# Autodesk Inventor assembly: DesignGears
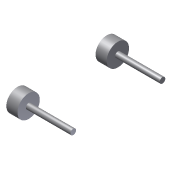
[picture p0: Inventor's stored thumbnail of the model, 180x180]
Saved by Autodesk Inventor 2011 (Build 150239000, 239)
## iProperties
Created: 2007-12
Part Number: DesignGears
Document SubType Name: Assembly
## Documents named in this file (2)
- C:\Data Folder\VEX 2011\Inventor Datasets\Unit 6\DesignGears.iam
- C:\Data Folder\VEX 2011\Inventor Datasets\Unit 6\Components\Shaft1.ipt
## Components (2 placed, 1 different names)
1. Shaft1:1
2. Shaft1:2
